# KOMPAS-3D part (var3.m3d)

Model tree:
1. ВЗ
2. jcm
     Расстояние = 75
3. ВЗ 1
     Расстояние = 50
4. ВЗ 2
     Расстояние = 50
5. ВЗ 3
     Расстояние = 50
6. ВЗ 4
     Расстояние = 50
7. ВЗ 5
     Расстояние = 50
8. ВЗ 6
     Расстояние = 50
9. Эскиз:9
10. Операция выдавливания:4
     Расстояние 1 = 65; Расстояние 2 = 60
11. Эскиз:10
12. Операция выдавливания:5
     Расстояние 1 = 65; Расстояние 2 = 70
13. Булева операция:2
14. Эскиз:11
15. Операция выдавливания:6
     Расстояние 1 = 545; Расстояние 2 = 360
16. Булева операция:3
17. Зеркальное отражение:3
18. ВЗ 7
     Расстояние = 50
19. ВЗ  8
     Расстояние = 50
20. боковые понтоны
21. Эскиз:21
22. Правый киль
     Толщина стенки 1 = 1; Толщина стенки 2 = 1; Расстояние 1 = 7; Расстояние 2 = 360
23. Левый киль
24. Киль1
25. Эскиз:22
26. Операция выдавливания:9
     Расстояние 1 = 125; Расстояние 2 = 125
27. стабилизатор1
28. Эскиз:24
29. Операция выдавливания:10
     Расстояние 1 = 75; Расстояние 2 = 75
30. Эскиз:25
31. Эскиз:26
32. Эскиз:27
33. Эскиз:30
34. Операция по сечениям:1
     Толщина стенки 1 = 2; Толщина стенки 2 = 2
35. Эскиз:28
36. Кинематическая операция:6
     Толщина стенки 1 = 2; Толщина стенки 2 = 14
37. Эскиз:29
38. Операция выдавливания:11
     Расстояние 1 = 45; Расстояние 2 = 45
39. Булева операция:8
40. Кабина2
41. сопло
     Толщина стенки 1 = 2; Толщина стенки 2 = 2
42. Эскиз:31
43. турбина 2
44. Смещенная плоскость:1
     Расстояние = 40
45. плоскости
46. Эскиз:40
47. Эскиз:41
48. Операция по сечениям:5
     Толщина стенки 1 = 2; Толщина стенки 2 = 2
49. задняя часть кабины
50. Эскиз:42
51. кабина1
     Толщина стенки 1 = 4; Толщина стенки 2 = 2
52. кабина
53. сечение губы
54. губа1
     Толщина стенки 1 = 4; Толщина стенки 2 = 2
55. губа
56. Корпус2
